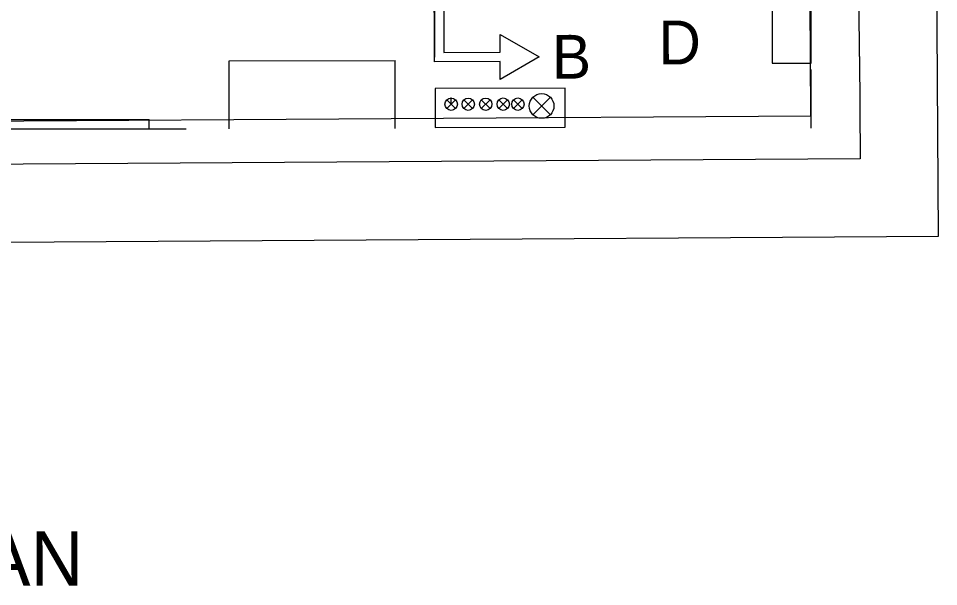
# Model space of a CAD drawing. Extents: x -2.6 to 16.3, y -2.7 to 7.5.
# Drawn here: x 10.11 to 16, y -2.14 to 1.5 of the extents above; entities that cross this region are included whole.
import ezdxf

# ---------------------------------------------------------------- set-up
doc = ezdxf.new("R2010")
doc.units = 0
for name, color, linetype in [('HS_Concrete_Object', 7, 'Continuous'), ('HS_Dimensions_and_Text', 7, 'Continuous'), ('HS_Electrical_Conduit', 7, 'Continuous'), ('HS_Electrical_Devices', 7, 'Continuous'), ('SH_Printer Plotting Border-ILTollway', 7, 'Continuous')]:
    doc.layers.add(name, color=color, linetype=linetype)

msp = doc.modelspace()

# ---------------------------------------------------------------- linework, layer by layer
at = {"layer": 'HS_Concrete_Object'}
msp.add_lwpolyline([(15.9556, 7.1018), (-0.0446, 6.9998), (0, 0), (16.0002, 0.1019)], close=True, dxfattribs=at)
for points in [[(15.1804, 1.2511), (15.1483, 6.2872)], [(15.4928, 1.2531), (15.462, 6.1014)], [(15.4928, 1.2531), (15.497, 0.5987), (7.1165, 0.5454)], [(15.1828, 0.8745), (15.1804, 1.2511)], [(7.1147, 0.823), (15.1828, 0.8745)]]:
    msp.add_lwpolyline(points, dxfattribs=at)
at = {"layer": 'HS_Dimensions_and_Text'}
msp.add_lwpolyline([(12.7609, 6.0463), (12.7712, 1.2501)], dxfattribs=at)
msp.add_lwpolyline([(13.4412, 1.2515), (13.1915, 1.1066), (13.1913, 1.2209), (12.7713, 1.22), (12.7699, 1.85), (12.8299, 1.8502), (12.8312, 1.2802), (13.1912, 1.2809), (13.1909, 1.3953)], close=True, dxfattribs=at)
at = {"layer": 'HS_Electrical_Conduit'}
msp.add_line((12.8777, 0.9478), (12.8777, 0.9904), dxfattribs=at)
at = {"layer": 'HS_Electrical_Devices'}
for p, q in [((11.4554, 1.226), (12.5181, 1.2269)), ((11.4558, 0.7909), (11.4554, 1.226)), ((12.5185, 0.7918), (12.5181, 1.2269)), ((12.9057, 0.9758), (12.8498, 0.9198)), ((12.9057, 0.9198), (12.8498, 0.9758)), ((13.0148, 0.9759), (12.9589, 0.9199)), ((13.0148, 0.9199), (12.9589, 0.9759)), ((13.1269, 0.976), (13.071, 0.92)), ((13.1269, 0.92), (13.071, 0.976)), ((13.239, 0.9761), (13.1831, 0.9201)), ((13.239, 0.9201), (13.1831, 0.9761)), ((13.333, 0.9762), (13.277, 0.9202)), ((13.333, 0.9202), (13.277, 0.9762)), ((13.5132, 0.8807), (13.4013, 0.9926)), ((13.4013, 0.8807), (13.5132, 0.9926))]:
    msp.add_line(p, q, dxfattribs=at)
for points in [[(15.1842, 1.2115), (15.1835, 2.0449), (14.9335, 2.0447), (14.9342, 1.2113)], [(13.6083, 1.0499), (12.775, 1.0491), (12.7752, 0.7991), (13.6086, 0.7999)]]:
    msp.add_lwpolyline(points, close=True, dxfattribs=at)
msp.add_lwpolyline([(15.1846, 0.7943), (15.1843, 1.1709)], dxfattribs=at)
for centre, radius in [((13.4572, 0.9367), 0.0791), ((12.8777, 0.9478), 0.0396), ((12.9868, 0.9479), 0.0396), ((13.099, 0.948), 0.0396), ((13.2111, 0.9481), 0.0396), ((13.305, 0.9482), 0.0396)]:
    msp.add_circle(centre, radius, dxfattribs=at)
at = {"layer": 'SH_Printer Plotting Border-ILTollway'}
for p, q in [((9.0404, 0.8485), (10.9436, 0.8502)), ((10.9437, 0.7904), (10.9436, 0.8502)), ((9.1718, 0.7887), (11.1809, 0.7906)), ((9.1718, 0.7887), (11.1809, 0.7906))]:
    msp.add_line(p, q, dxfattribs=at)

# ---------------------------------------------------------------- texts
at = {"layer": 'HS_Dimensions_and_Text'}
for s, rotation, p in [('D', 0.16742, (14.2065, 1.2026)), ('B', 0.12312, (13.5237, 1.1113))]:
    msp.add_text(s, height=0.2808, rotation=rotation, dxfattribs=at).set_placement(p)
msp.add_text('IPDC FACILITY SITE PLAN', height=0.35, dxfattribs=at).set_placement((4.6957, -2.1373))

doc.saveas('drawing.dxf')
